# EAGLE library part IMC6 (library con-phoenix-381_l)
Invertierter Mini-Combicon 3.81mm horizontal 6-polig IMC 1,5/6-G-3,81 (ohne Gegenstecker)
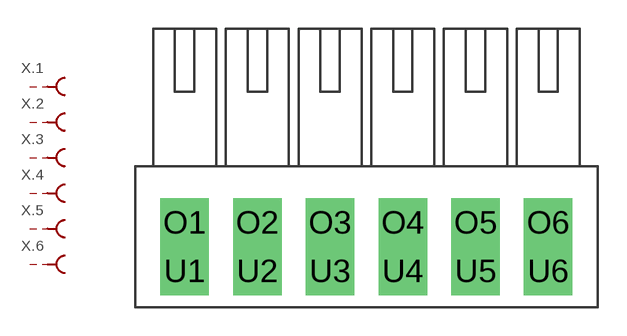
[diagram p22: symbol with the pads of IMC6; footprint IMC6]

Designator prefix X; gates .3=MCBU .2=MCBU .1=MCBU .4=MCBU .5=MCBU .6=MCBU

## IMC6  [IMC6]
O1  .1:S  pas
O2  .2:S  pas
O3  .3:S  pas
O4  .4:S  pas
O5  .5:S  pas
O6  .6:S  pas
U1  .1:SK  pas
U2  .2:SK  pas
U3  .3:SK  pas
U4  .4:SK  pas
U5  .5:SK  pas
U6  .6:SK  pas

## Footprint IMC6 (pad centres in mm)
Mini-Combicon 3.81mm horizontal 6-polig invertiert (ohne Gegenstecker)
drill 1.3 pad 2.54 square: O1 -9.525,1.27; O2 -5.715,1.27; O3 -1.905,1.27; O4 1.905,1.27; O5 5.715,1.27; O6 9.525,1.27; U1 -9.525,-1.27; U2 -5.715,-1.27; U3 -1.905,-1.27; U4 1.905,-1.27; U5 5.715,-1.27; U6 9.525,-1.27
